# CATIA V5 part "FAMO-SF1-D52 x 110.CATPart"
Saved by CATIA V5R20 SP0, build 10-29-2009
Part number: FAMO-SF1-D52 x 110
Definition: NONE
Nomenclature: FAMO-SF1-D52 x 110
Source: Unknown
Description: FAMO-SF1-D52 x 110
Bounding box of the stored display mesh (mm): x -53 to 57, y -39.5 to 39.5, z -39.5 to 39.5
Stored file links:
  C:\Users\Utente\Desktop\IO LAVORO\3D X SITO CF\X SITO\FAMO\FAMO-SF1-D52 x 110.CATPart

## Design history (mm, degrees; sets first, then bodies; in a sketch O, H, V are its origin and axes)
Body1 "FAMO-SF1-D52 x 110" (main body)
  Solid1: solid without history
